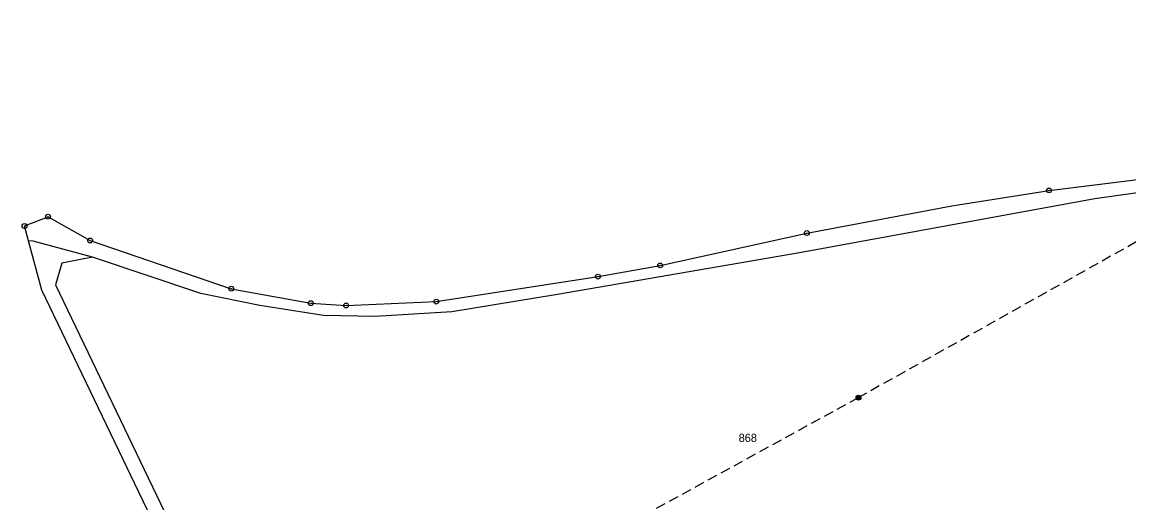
# Model space of a CAD drawing. Extents: x -754445 to -751443, y -1030748 to -1028224.
# Drawn here: x -754444.8 to -754214.8, y -1028563 to -1028463.2 of the extents above; entities that cross this region are included whole.
import ezdxf
from ezdxf.enums import TextEntityAlignment as Align

# ---------------------------------------------------------------- set-up
doc = ezdxf.new("R2010")
doc.units = 0
doc.header["$LTSCALE"] = 0.68
doc.linetypes.add('MEDIUM_DASHED', pattern=[4.5, 3, -1.5])
for name, color, linetype, lineweight in [('1', 7, 'Continuous', 25), ('6', 7, 'Continuous', 25), ('8', 7, 'Continuous', 25)]:
    doc.layers.add(name, color=color, linetype=linetype, lineweight=lineweight)
doc.layers.add('2', color=7, linetype='Continuous')

msp = doc.modelspace()

# ---------------------------------------------------------------- linework, layer by layer
at = {"layer": '1'}
for p, q in [((-754444.28, -1028505.53), (-754439.4, -1028503.6)), ((-754443.45, -1028508.59), (-754444.28, -1028505.53)), ((-754384.79, -1028521.55), (-754377.46, -1028522.03))]:
    msp.add_line(p, q, dxfattribs=at)
for points in [[(-754377.46, -1028522.03), (-754358.71, -1028521.23), (-754325.11, -1028516.04), (-754312.19, -1028513.72), (-754281.72, -1028507), (-754251.56, -1028501.34), (-754231.39, -1028498.15), (-754176.29, -1028491.34), (-754158.58, -1028490.31), (-754128.79, -1028489.96), (-754089.82, -1028493.19), (-754058.44, -1028499.31), (-754032.41, -1028505.8), (-754008.62, -1028508.97), (-753982.13, -1028510.26), (-753970.76, -1028509.09), (-753947.34, -1028503.16)], [(-754121.75, -1028492.72), (-754147.39, -1028493.13), (-754160.91, -1028492.63), (-754186.92, -1028494.98), (-754221.86, -1028499.87), (-754283.24, -1028511.12), (-754333.56, -1028519.77), (-754355.47, -1028523.36), (-754371.45, -1028524.31), (-754382.14, -1028524.15), (-754395.41, -1028522.06), (-754407.62, -1028519.52), (-754430.14, -1028511.99)], [(-754439.4, -1028503.6), (-754430.65, -1028508.55), (-754401.32, -1028518.55), (-754384.79, -1028521.55)], [(-754430.14, -1028511.99), (-754442.47, -1028508.65), (-754443.45, -1028508.59)], [(-754417.11, -1028567.89), (-754440.66, -1028518.83), (-754443.45, -1028508.59)], [(-754430.14, -1028511.99), (-754436.5, -1028513.24), (-754437.84, -1028517.78), (-754414.38, -1028566.64), (-754395.28, -1028610.38), (-754373.32, -1028644.38), (-754362.3, -1028659.99), (-754346.92, -1028678.42), (-754346.48, -1028678.27), (-754326.97, -1028665.65), (-754325.34, -1028668.17)]]:
    msp.add_lwpolyline(points, dxfattribs=at)
at = {"layer": '6', "linetype": 'MEDIUM_DASHED'}
msp.add_lwpolyline([(-754129.99, -1028463.21), (-754199.91, -1028501.36), (-754270.98, -1028541.17), (-754341.02, -1028579.57), (-754412.06, -1028618.91)], dxfattribs=at)
at = {"layer": '6'}
for radius in [0.5, 0.4, 0.3, 0.2, 0.1]:
    msp.add_circle((-754270.9834, -1028541.1699), radius, dxfattribs=at)
at = {"layer": '8'}
for centre, radius in [((-754231.39, -1028498.1499), 0.5), ((-754231.39, -1028498.1499), 0.0303), ((-754439.4, -1028503.5999), 0.5), ((-754439.4, -1028503.5999), 0.0303), ((-754444.28, -1028505.5299), 0.5), ((-754444.28, -1028505.5299), 0.0303), ((-754281.72, -1028506.9999), 0.5), ((-754281.72, -1028506.9999), 0.0303), ((-754430.65, -1028508.5499), 0.5), ((-754430.65, -1028508.5499), 0.0303), ((-754312.19, -1028513.7199), 0.5), ((-754312.19, -1028513.7199), 0.0303), ((-754325.11, -1028516.0399), 0.5), ((-754325.11, -1028516.0399), 0.0303), ((-754401.32, -1028518.5499), 0.5), ((-754401.32, -1028518.5499), 0.0303), ((-754358.71, -1028521.2299), 0.5), ((-754384.79, -1028521.5499), 0.5), ((-754384.79, -1028521.5499), 0.0303), ((-754377.46, -1028522.0299), 0.5), ((-754377.46, -1028522.0299), 0.0303), ((-754358.71, -1028521.2299), 0.0303)]:
    msp.add_circle(centre, radius, dxfattribs=at)

# ---------------------------------------------------------------- texts
at = {"layer": '2'}
msp.add_text('868', height=1.7, dxfattribs=at).set_placement((-754293.989, -1028550.376), align=Align.CENTER)

doc.saveas('drawing.dxf')
